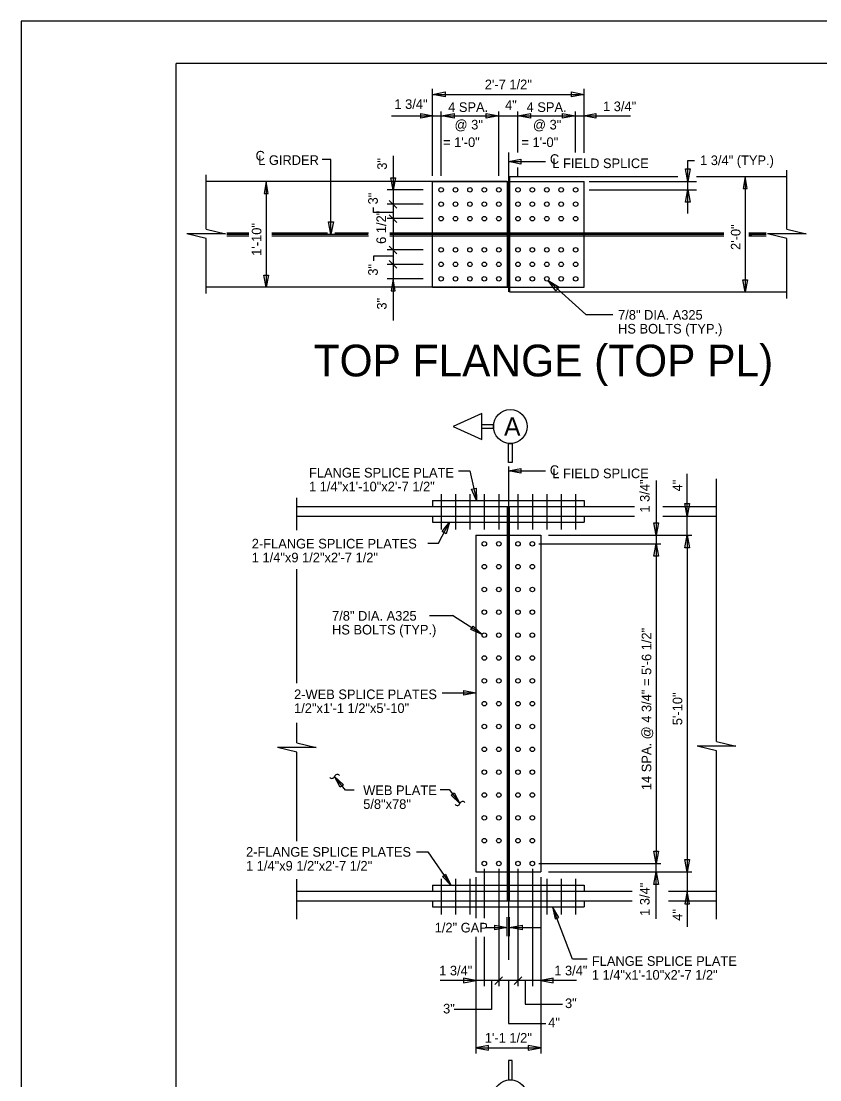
# Model space of a CAD drawing. Extents: x 1970675.2 to 1970715, y 796143 to 796167.2.
# Drawn here: x 1970675.24 to 1970685.62, y 796153.49 to 796167.25 of the extents above; entities that cross this region are included whole.
import ezdxf

# ---------------------------------------------------------------- set-up
doc = ezdxf.new("R2010")
doc.units = 0
for name, color, linetype in [('BR_AUTO DIMENSION', 7, 'Continuous'), ('BR_BORDER LINES', 7, 'Continuous'), ('BR_CENTER LINES', 7, 'Continuous'), ('BR_STRUCTURAL STEEL', 7, 'Continuous'), ('BR_TEXT', 7, 'Continuous'), ('Default', 7, 'Continuous'), ('Level 31', 7, 'Continuous')]:
    doc.layers.add(name, color=color, linetype=linetype)

msp = doc.modelspace()

# ---------------------------------------------------------------- linework, layer by layer
at = {"layer": 'BR_AUTO DIMENSION'}
for p, q in [((1970680.588, 796165.236), (1970680.588, 796166.368)), ((1970680.588, 796166.295), (1970682.557, 796166.295)), ((1970682.557, 796165.537), (1970682.557, 796166.366)), ((1970680.698, 796165.236), (1970680.698, 796166.071)), ((1970681.448, 796165.236), (1970681.448, 796166.071)), ((1970681.698, 796165.538), (1970681.698, 796166.071)), ((1970682.448, 796165.538), (1970682.448, 796166.071)), ((1970680.053, 796166.015), (1970683.16, 796166.015)), ((1970680.073, 796165.497), (1970680.073, 796163.356)), ((1970679.266, 796165.447), (1970679.15, 796165.447)), ((1970679.266, 796164.477), (1970679.266, 796165.447)), ((1970681.698, 796165.236), (1970681.698, 796165.343)), ((1970683.908, 796164.749), (1970683.908, 796165.436)), ((1970683.908, 796165.436), (1970683.995, 796165.436)), ((1970684.652, 796165.227), (1970684.652, 796163.727)), ((1970678.422, 796165.164), (1970678.422, 796163.789)), ((1970680.466, 796165.055), (1970679.998, 796165.055)), ((1970682.624, 796165.164), (1970684.018, 796165.164)), ((1970682.624, 796165.055), (1970684.018, 796165.055)), ((1970680.123, 796164.817), (1970680.024, 796164.918)), ((1970680.466, 796164.868), (1970679.998, 796164.868)), ((1970680.466, 796164.68), (1970679.998, 796164.68)), ((1970680.123, 796164.629), (1970680.024, 796164.731)), ((1970680.466, 796164.274), (1970679.998, 796164.274)), ((1970680.123, 796164.223), (1970680.024, 796164.324)), ((1970680.123, 796164.036), (1970680.024, 796164.137)), ((1970680.466, 796164.086), (1970679.998, 796164.086)), ((1970680.466, 796163.899), (1970679.998, 796163.899)), ((1970682.582, 796163.436), (1970682.091, 796163.876)), ((1970682.582, 796163.436), (1970682.93, 796163.436)), ((1970680.926, 796161.404), (1970681.072, 796161.404)), ((1970681.072, 796161.404), (1970681.159, 796161.018)), ((1970683.897, 796160.565), (1970683.897, 796161.365)), ((1970683.495, 796161.279), (1970683.495, 796160.455)), ((1970680.663, 796160.461), (1970680.809, 796160.736)), ((1970682.096, 796160.565), (1970683.96, 796160.565)), ((1970683.897, 796160.565), (1970683.897, 796156.19)), ((1970680.527, 796160.461), (1970680.663, 796160.461)), ((1970681.971, 796160.455), (1970683.557, 796160.455)), ((1970683.495, 796160.455), (1970683.495, 796156.299)), ((1970680.548, 796159.522), (1970680.845, 796159.522)), ((1970681.233, 796159.278), (1970680.845, 796159.522)), ((1970680.713, 796158.517), (1970681.151, 796158.517)), ((1970679.453, 796157.251), (1970679.312, 796157.432)), ((1970679.568, 796157.251), (1970679.453, 796157.251)), ((1970680.688, 796157.261), (1970680.802, 796157.261)), ((1970680.802, 796157.261), (1970680.943, 796157.08)), ((1970680.378, 796156.451), (1970680.524, 796156.451)), ((1970680.524, 796156.451), (1970680.825, 796156.018)), ((1970681.971, 796156.299), (1970683.557, 796156.299)), ((1970683.495, 796155.58), (1970683.495, 796156.299)), ((1970681.151, 796156.122), (1970681.151, 796155.589)), ((1970681.26, 796156.231), (1970681.26, 796155.589)), ((1970681.448, 796156.231), (1970681.448, 796154.706)), ((1970681.698, 796156.231), (1970681.698, 796154.706)), ((1970681.885, 796156.231), (1970681.885, 796154.706)), ((1970681.995, 796156.122), (1970681.995, 796153.832)), ((1970682.096, 796156.19), (1970683.96, 796156.19)), ((1970683.897, 796156.19), (1970683.897, 796155.477)), ((1970682.408, 796155.056), (1970682.149, 796155.736)), ((1970681.557, 796155.355), (1970681.557, 796155.601)), ((1970681.588, 796155.355), (1970681.588, 796155.601)), ((1970681.27, 796155.467), (1970681.557, 796155.467)), ((1970681.588, 796155.467), (1970682.004, 796155.467)), ((1970681.151, 796155.347), (1970681.151, 796153.832)), ((1970681.26, 796155.347), (1970681.26, 796154.706)), ((1970682.6, 796155.056), (1970682.408, 796155.056)), ((1970682.458, 796154.779), (1970680.687, 796154.779)), ((1970681.354, 796154.779), (1970681.354, 796154.401)), ((1970681.498, 796154.829), (1970681.397, 796154.729)), ((1970681.573, 796154.779), (1970681.573, 796154.221)), ((1970681.748, 796154.829), (1970681.647, 796154.729)), ((1970681.791, 796154.779), (1970681.791, 796154.471)), ((1970681.791, 796154.471), (1970682.278, 796154.471)), ((1970681.354, 796154.401), (1970680.868, 796154.401)), ((1970681.573, 796154.221), (1970682.059, 796154.221)), ((1970681.151, 796153.905), (1970681.995, 796153.905))]:
    msp.add_line(p, q, dxfattribs=at)
for points in [[(1970680.751, 796166.264), (1970680.588, 796166.295), (1970680.751, 796166.326)], [(1970682.395, 796166.326), (1970682.557, 796166.295), (1970682.395, 796166.264)], [(1970680.434, 796166.046), (1970680.596, 796166.015), (1970680.434, 796165.984)], [(1970680.868, 796165.984), (1970680.705, 796166.015), (1970680.868, 796166.046)], [(1970681.285, 796166.046), (1970681.448, 796166.015), (1970681.285, 796165.984)], [(1970681.86, 796165.984), (1970681.698, 796166.015), (1970681.86, 796166.046)], [(1970682.277, 796166.046), (1970682.44, 796166.015), (1970682.277, 796165.984)], [(1970682.712, 796165.984), (1970682.549, 796166.015), (1970682.712, 796166.046)], [(1970681.735, 796165.389), (1970681.573, 796165.421), (1970681.735, 796165.452)], [(1970680.103, 796165.211), (1970680.073, 796165.055), (1970680.043, 796165.211)], [(1970683.939, 796165.327), (1970683.908, 796165.164), (1970683.877, 796165.327)], [(1970684.626, 796165.071), (1970684.678, 796165.071), (1970684.652, 796165.227)], [(1970678.396, 796165.008), (1970678.448, 796165.008), (1970678.422, 796165.164)], [(1970683.877, 796164.893), (1970683.908, 796165.055), (1970683.939, 796164.893)], [(1970679.297, 796164.639), (1970679.266, 796164.477), (1970679.235, 796164.639)], [(1970678.452, 796163.945), (1970678.422, 796163.789), (1970678.392, 796163.945)], [(1970680.047, 796163.742), (1970680.099, 796163.742), (1970680.073, 796163.899)], [(1970682.191, 796163.744), (1970682.091, 796163.876), (1970682.233, 796163.791)], [(1970684.682, 796163.883), (1970684.652, 796163.727), (1970684.622, 796163.883)], [(1970681.735, 796161.371), (1970681.573, 796161.403), (1970681.735, 796161.434)], [(1970681.154, 796161.176), (1970681.159, 796161.018), (1970681.095, 796161.163)], [(1970683.929, 796160.977), (1970683.897, 796160.815), (1970683.866, 796160.977)], [(1970680.71, 796160.613), (1970680.809, 796160.736), (1970680.762, 796160.585)], [(1970683.526, 796160.727), (1970683.495, 796160.565), (1970683.463, 796160.727)], [(1970683.866, 796160.402), (1970683.897, 796160.565), (1970683.929, 796160.402)], [(1970683.463, 796160.293), (1970683.495, 796160.455), (1970683.526, 796160.293)], [(1970681.086, 796159.339), (1970681.114, 796159.383), (1970681.233, 796159.278)], [(1970680.995, 796158.547), (1970681.151, 796158.517), (1970680.995, 796158.487)], [(1970679.429, 796157.324), (1970679.387, 796157.292), (1970679.312, 796157.432)], [(1970680.827, 796157.187), (1970680.868, 796157.219), (1970680.943, 796157.08)], [(1970683.526, 796156.461), (1970683.495, 796156.299), (1970683.463, 796156.461)], [(1970683.929, 796156.352), (1970683.897, 796156.19), (1970683.866, 796156.352)], [(1970680.715, 796156.131), (1970680.757, 796156.161), (1970680.825, 796156.018)], [(1970683.463, 796156.027), (1970683.495, 796156.19), (1970683.526, 796156.027)], [(1970683.929, 796155.777), (1970683.897, 796155.94), (1970683.866, 796155.777)], [(1970682.182, 796155.581), (1970682.23, 796155.6), (1970682.149, 796155.736)], [(1970681.395, 796155.498), (1970681.557, 796155.467), (1970681.395, 796155.436)], [(1970681.751, 796155.436), (1970681.588, 796155.467), (1970681.751, 796155.498)], [(1970680.988, 796154.748), (1970681.151, 796154.779), (1970680.988, 796154.81)], [(1970682.157, 796154.81), (1970681.995, 796154.779), (1970682.157, 796154.748)], [(1970681.313, 796153.936), (1970681.151, 796153.905), (1970681.313, 796153.874)], [(1970681.832, 796153.874), (1970681.995, 796153.905), (1970681.832, 796153.936)]]:
    msp.add_lwpolyline(points, close=True, dxfattribs=at)
for points in [[(1970681.573, 796165.421), (1970682.058, 796165.421)], [(1970680.073, 796164.762), (1970679.82, 796164.762), (1970679.82, 796164.823)], [(1970680.073, 796164.192), (1970679.82, 796164.192), (1970679.82, 796164.131)], [(1970681.573, 796161.403), (1970682.058, 796161.403)]]:
    msp.add_lwpolyline(points, dxfattribs=at)
at = {"layer": 'BR_BORDER LINES'}
for p in [(1970714.286, 796166.696), (1970677.253, 796143.596)]:
    msp.add_line(p, (1970677.253, 796166.696), dxfattribs=at)
at = {"layer": 'BR_CENTER LINES'}
for p, q in [((1970681.573, 796165.541), (1970681.573, 796163.727)), ((1970677.911, 796164.477), (1970678.196, 796164.477)), ((1970678.495, 796164.477), (1970679.266, 796164.477)), ((1970679.266, 796164.477), (1970679.75, 796164.477)), ((1970680.033, 796164.477), (1970684.377, 796164.477)), ((1970684.7, 796164.477), (1970684.924, 796164.477)), ((1970684.7, 796164.477), (1970684.74, 796164.477)), ((1970681.573, 796161.459), (1970681.573, 796155.048))]:
    msp.add_line(p, q, dxfattribs=at)
at = {"layer": 'BR_STRUCTURAL STEEL'}
for p, q in [((1970681.588, 796165.227), (1970683.778, 796165.227)), ((1970681.588, 796165.227), (1970681.588, 796165.164)), ((1970684.019, 796165.227), (1970685.195, 796165.227)), ((1970681.557, 796165.164), (1970677.643, 796165.164)), ((1970680.588, 796163.789), (1970680.588, 796165.164)), ((1970680.588, 796165.164), (1970682.557, 796165.164)), ((1970681.557, 796165.164), (1970681.557, 796163.789)), ((1970681.588, 796165.164), (1970681.588, 796163.789)), ((1970682.557, 796163.789), (1970682.557, 796165.164)), ((1970677.911, 796164.496), (1970678.196, 796164.496)), ((1970677.911, 796164.457), (1970678.196, 796164.457)), ((1970678.495, 796164.496), (1970679.221, 796164.496)), ((1970678.495, 796164.457), (1970679.752, 796164.457)), ((1970679.316, 796164.496), (1970679.752, 796164.496)), ((1970680.032, 796164.496), (1970681.557, 796164.496)), ((1970680.032, 796164.457), (1970681.557, 796164.457)), ((1970681.588, 796164.496), (1970684.376, 796164.496)), ((1970681.588, 796164.457), (1970684.377, 796164.457)), ((1970684.7, 796164.496), (1970684.924, 796164.496)), ((1970684.7, 796164.457), (1970684.924, 796164.457)), ((1970684.702, 796164.461), (1970684.74, 796164.461)), ((1970681.557, 796163.789), (1970677.643, 796163.789)), ((1970680.588, 796163.789), (1970682.557, 796163.789)), ((1970681.588, 796163.789), (1970681.588, 796163.727)), ((1970681.588, 796163.727), (1970685.195, 796163.727)), ((1970680.698, 796161.099), (1970680.698, 796160.639)), ((1970680.885, 796161.099), (1970680.885, 796160.639)), ((1970681.073, 796161.099), (1970681.073, 796160.639)), ((1970681.26, 796161.099), (1970681.26, 796160.639)), ((1970681.448, 796161.099), (1970681.448, 796160.639)), ((1970681.698, 796161.099), (1970681.698, 796160.639)), ((1970681.885, 796161.099), (1970681.885, 796160.639)), ((1970682.073, 796161.099), (1970682.073, 796160.639)), ((1970682.26, 796161.099), (1970682.26, 796160.639)), ((1970682.448, 796161.099), (1970682.448, 796160.639)), ((1970678.823, 796160.94), (1970683.214, 796160.94)), ((1970680.588, 796161.018), (1970680.588, 796160.94)), ((1970680.588, 796161.018), (1970682.557, 796161.018)), ((1970680.588, 796160.94), (1970682.557, 796160.94)), ((1970681.557, 796160.94), (1970681.557, 796155.815)), ((1970681.588, 796155.815), (1970681.588, 796160.94)), ((1970682.557, 796161.018), (1970682.557, 796160.94)), ((1970683.582, 796160.94), (1970684.281, 796160.94)), ((1970678.823, 796160.815), (1970683.214, 796160.815)), ((1970680.588, 796160.815), (1970680.588, 796160.736)), ((1970680.588, 796160.815), (1970682.557, 796160.815)), ((1970682.557, 796160.815), (1970682.557, 796160.736)), ((1970683.582, 796160.815), (1970684.281, 796160.815)), ((1970680.588, 796160.736), (1970682.557, 796160.736)), ((1970681.151, 796160.565), (1970681.995, 796160.565)), ((1970681.151, 796160.565), (1970681.151, 796156.19)), ((1970681.995, 796160.565), (1970681.995, 796156.19)), ((1970681.151, 796156.19), (1970681.995, 796156.19)), ((1970680.588, 796156.018), (1970680.588, 796155.94)), ((1970680.588, 796156.018), (1970682.557, 796156.018)), ((1970680.698, 796156.099), (1970680.698, 796155.639)), ((1970680.885, 796156.099), (1970680.885, 796155.639)), ((1970681.073, 796156.099), (1970681.073, 796155.639)), ((1970681.26, 796156.099), (1970681.26, 796155.589)), ((1970681.448, 796156.099), (1970681.448, 796155.639)), ((1970681.698, 796156.099), (1970681.698, 796155.639)), ((1970681.885, 796156.099), (1970681.885, 796155.639)), ((1970682.073, 796156.099), (1970682.073, 796155.639)), ((1970682.26, 796156.099), (1970682.26, 796155.639)), ((1970682.448, 796156.099), (1970682.448, 796155.639)), ((1970682.557, 796156.018), (1970682.557, 796155.94)), ((1970678.823, 796155.94), (1970683.183, 796155.94)), ((1970680.588, 796155.94), (1970682.557, 796155.94)), ((1970683.655, 796155.94), (1970684.281, 796155.94)), ((1970678.823, 796155.815), (1970683.183, 796155.815)), ((1970680.588, 796155.815), (1970680.588, 796155.736)), ((1970680.588, 796155.815), (1970682.557, 796155.815)), ((1970680.588, 796155.736), (1970682.557, 796155.736)), ((1970682.557, 796155.815), (1970682.557, 796155.736)), ((1970683.655, 796155.815), (1970684.281, 796155.815))]:
    msp.add_line(p, q, dxfattribs=at)
for centre in [(1970680.698, 796165.055), (1970680.698, 796165.055), (1970680.885, 796165.055), (1970680.885, 796165.055), (1970681.073, 796165.055), (1970681.073, 796165.055), (1970681.26, 796165.055), (1970681.26, 796165.055), (1970681.448, 796165.055), (1970681.448, 796165.055), (1970681.698, 796165.055), (1970681.698, 796165.055), (1970681.885, 796165.055), (1970681.885, 796165.055), (1970682.073, 796165.055), (1970682.073, 796165.055), (1970682.26, 796165.055), (1970682.26, 796165.055), (1970682.448, 796165.055), (1970682.448, 796165.055), (1970680.698, 796164.868), (1970680.698, 796164.868), (1970680.885, 796164.868), (1970680.885, 796164.868), (1970681.073, 796164.868), (1970681.073, 796164.868), (1970681.26, 796164.868), (1970681.26, 796164.868), (1970681.448, 796164.868), (1970681.448, 796164.868), (1970681.698, 796164.868), (1970681.698, 796164.868), (1970681.885, 796164.868), (1970681.885, 796164.868), (1970682.073, 796164.868), (1970682.073, 796164.868), (1970682.26, 796164.868), (1970682.26, 796164.868), (1970682.448, 796164.868), (1970682.448, 796164.868), (1970680.698, 796164.68), (1970680.698, 796164.68), (1970680.885, 796164.68), (1970680.885, 796164.68), (1970681.073, 796164.68), (1970681.073, 796164.68), (1970681.26, 796164.68), (1970681.26, 796164.68), (1970681.448, 796164.68), (1970681.448, 796164.68), (1970681.698, 796164.68), (1970681.698, 796164.68), (1970681.885, 796164.68), (1970681.885, 796164.68), (1970682.073, 796164.68), (1970682.073, 796164.68), (1970682.26, 796164.68), (1970682.26, 796164.68), (1970682.448, 796164.68), (1970682.448, 796164.68), (1970680.698, 796164.274), (1970680.698, 796164.274), (1970680.885, 796164.274), (1970680.885, 796164.274), (1970681.073, 796164.274), (1970681.073, 796164.274), (1970681.26, 796164.274), (1970681.26, 796164.274), (1970681.448, 796164.274), (1970681.448, 796164.274), (1970681.698, 796164.274), (1970681.698, 796164.274), (1970681.885, 796164.274), (1970681.885, 796164.274), (1970682.073, 796164.274), (1970682.073, 796164.274), (1970682.26, 796164.274), (1970682.26, 796164.274), (1970682.448, 796164.274), (1970682.448, 796164.274), (1970680.698, 796164.086), (1970680.698, 796164.086), (1970680.885, 796164.086), (1970680.885, 796164.086), (1970681.073, 796164.086), (1970681.073, 796164.086), (1970681.26, 796164.086), (1970681.26, 796164.086), (1970681.448, 796164.086), (1970681.448, 796164.086), (1970681.698, 796164.086), (1970681.698, 796164.086), (1970681.885, 796164.086), (1970681.885, 796164.086), (1970682.073, 796164.086), (1970682.073, 796164.086), (1970682.26, 796164.086), (1970682.26, 796164.086), (1970682.448, 796164.086), (1970682.448, 796164.086), (1970680.698, 796163.899), (1970680.698, 796163.899), (1970680.885, 796163.899), (1970680.885, 796163.899), (1970681.073, 796163.899), (1970681.073, 796163.899), (1970681.26, 796163.899), (1970681.26, 796163.899), (1970681.448, 796163.899), (1970681.448, 796163.899), (1970681.698, 796163.899), (1970681.698, 796163.899), (1970681.885, 796163.899), (1970681.885, 796163.899), (1970682.073, 796163.899), (1970682.073, 796163.899), (1970682.26, 796163.899), (1970682.26, 796163.899), (1970682.448, 796163.899), (1970682.448, 796163.899), (1970681.26, 796160.455), (1970681.448, 796160.455), (1970681.698, 796160.455), (1970681.885, 796160.455), (1970681.26, 796160.158), (1970681.448, 796160.158), (1970681.698, 796160.158), (1970681.885, 796160.158), (1970681.26, 796159.861), (1970681.448, 796159.861), (1970681.698, 796159.861), (1970681.885, 796159.861), (1970681.26, 796159.565), (1970681.448, 796159.565), (1970681.698, 796159.565), (1970681.885, 796159.565), (1970681.26, 796159.268), (1970681.448, 796159.268), (1970681.698, 796159.268), (1970681.885, 796159.268), (1970681.26, 796158.971), (1970681.448, 796158.971), (1970681.698, 796158.971), (1970681.885, 796158.971), (1970681.26, 796158.674), (1970681.448, 796158.674), (1970681.698, 796158.674), (1970681.885, 796158.674), (1970681.26, 796158.377), (1970681.448, 796158.377), (1970681.698, 796158.377), (1970681.885, 796158.377), (1970681.26, 796158.08), (1970681.448, 796158.08), (1970681.698, 796158.08), (1970681.885, 796158.08), (1970681.26, 796157.783), (1970681.448, 796157.783), (1970681.698, 796157.783), (1970681.885, 796157.783), (1970681.26, 796157.486), (1970681.448, 796157.486), (1970681.698, 796157.486), (1970681.885, 796157.486), (1970681.26, 796157.19), (1970681.448, 796157.19), (1970681.698, 796157.19), (1970681.885, 796157.19), (1970681.26, 796156.893), (1970681.448, 796156.893), (1970681.698, 796156.893), (1970681.885, 796156.893), (1970681.26, 796156.596), (1970681.448, 796156.596), (1970681.698, 796156.596), (1970681.885, 796156.596), (1970681.26, 796156.299), (1970681.448, 796156.299), (1970681.698, 796156.299), (1970681.885, 796156.299)]:
    msp.add_circle(centre, 0.0293, dxfattribs=at)
at = {"layer": 'BR_TEXT'}
for points in [[(1970681.229, 796162.148), (1970680.853, 796161.979), (1970681.229, 796161.81)], [(1970681.379, 796161.954), (1970681.229, 796161.954), (1970681.229, 796162.004), (1970681.379, 796162.004)], [(1970681.623, 796161.51), (1970681.573, 796161.51), (1970681.573, 796161.76), (1970681.623, 796161.76)], [(1970681.623, 796153.739), (1970681.573, 796153.739), (1970681.573, 796153.489), (1970681.623, 796153.489)]]:
    msp.add_lwpolyline(points, close=True, dxfattribs=at)
for centre in [(1970681.598, 796161.979), (1970681.598, 796153.27)]:
    msp.add_circle(centre, 0.219, dxfattribs=at)
at = {"layer": 'Default'}
for p, q in [((1970677.643, 796164.543), (1970677.643, 796165.248)), ((1970685.195, 796164.543), (1970685.195, 796165.31)), ((1970677.643, 796164.543), (1970677.895, 796164.482)), ((1970685.195, 796164.543), (1970685.447, 796164.482)), ((1970677.895, 796164.482), (1970677.391, 796164.482)), ((1970677.643, 796164.422), (1970677.391, 796164.482)), ((1970677.643, 796163.706), (1970677.643, 796164.422)), ((1970685.447, 796164.482), (1970684.944, 796164.482)), ((1970685.195, 796164.422), (1970684.944, 796164.482)), ((1970685.195, 796163.644), (1970685.195, 796164.422)), ((1970684.281, 796157.884), (1970684.281, 796161.297)), ((1970678.823, 796160.633), (1970678.823, 796161.054)), ((1970678.823, 796158.643), (1970678.823, 796160.127)), ((1970678.823, 796157.868), (1970678.823, 796158.13)), ((1970679.074, 796157.807), (1970678.571, 796157.807)), ((1970678.823, 796157.747), (1970678.571, 796157.807)), ((1970678.823, 796157.868), (1970679.074, 796157.807)), ((1970684.532, 796157.823), (1970684.029, 796157.823)), ((1970684.281, 796157.763), (1970684.029, 796157.823)), ((1970684.281, 796157.884), (1970684.532, 796157.823)), ((1970684.281, 796155.575), (1970684.281, 796157.763)), ((1970678.823, 796156.589), (1970678.823, 796157.747)), ((1970678.823, 796155.575), (1970678.823, 796156.098))]:
    msp.add_line(p, q, dxfattribs=at)
for centre, start, end in [((1970679.277, 796157.443), 219.9477, 342.4119), ((1970679.347, 796157.421), 39.9477, 162.4119), ((1970680.908, 796157.091), 219.9477, 342.4119), ((1970680.978, 796157.069), 39.9477, 162.4119)]:
    msp.add_arc(centre, 0.0366, start, end, dxfattribs=at)
at = {"layer": 'Level 31'}
msp.add_line((1970714.836, 796167.246), (1970675.236, 796167.246), dxfattribs=at)
msp.add_lwpolyline([(1970675.236, 796167.246), (1970675.236, 796143.046), (1970714.836, 796143.046), (1970714.836, 796167.246)], dxfattribs=at)

# ---------------------------------------------------------------- texts
at = {"layer": 'BR_AUTO DIMENSION'}
for s, p in [('1 3/4"', (1970683.41, 796160.859)), ('4"', (1970683.835, 796161.135)), ('14 SPA. @ 4 3/4" = 5\'-6 1/2"', (1970683.432, 796157.253)), ('5\'-10"', (1970683.835, 796158.097)), ('1 3/4"', (1970683.41, 796155.619)), ('4"', (1970683.835, 796155.555))]:
    msp.add_text(s, height=0.125, rotation=90, dxfattribs=at).set_placement(p)
at = {"layer": 'BR_TEXT'}
for s, height, p in [('2\'-7 1/2"', 0.125, (1970681.267, 796166.362)), ('1 3/4"', 0.125, (1970680.091, 796166.106)), ('4 SPA. ', 0.125, (1970680.79, 796166.067)), ('4"', 0.125, (1970681.53, 796166.093)), ('4 SPA. ', 0.125, (1970681.81, 796166.067)), ('1 3/4"', 0.125, (1970682.804, 796166.077)), ('@ 3" ', 0.125, (1970680.873, 796165.839)), ('@ 3" ', 0.125, (1970681.893, 796165.839)), ('= 1\'-0"', 0.125, (1970680.724, 796165.611)), ('= 1\'-0"', 0.125, (1970681.744, 796165.611)), ('C', 0.125, (1970678.285, 796165.435)), ('L GIRDER', 0.125, (1970678.319, 796165.378)), ('C', 0.125, (1970682.113, 796165.392)), ('1 3/4" (TYP.)', 0.125, (1970684.066, 796165.376)), ('L FIELD SPLICE', 0.125, (1970682.144, 796165.337)), ('7/8" DIA. A325', 0.125, (1970683, 796163.367)), ('HS BOLTS (TYP.)', 0.125, (1970683, 796163.187)), ('TOP FLANGE (TOP PL)', 0.4125, (1970679.041, 796162.63)), ('A', 0.24, (1970681.517, 796161.859)), ('C', 0.125, (1970682.112, 796161.349)), ('FLANGE SPLICE PLATE', 0.125, (1970678.98, 796161.316)), ('L FIELD SPLICE', 0.125, (1970682.144, 796161.307)), ('1 1/4"x1\'-10"x2\'-7 1/2"', 0.125, (1970678.98, 796161.136)), ('2-FLANGE SPLICE PLATES', 0.125, (1970678.236, 796160.394)), ('1 1/4"x9 1/2"x2\'-7 1/2"', 0.125, (1970678.236, 796160.214)), ('7/8" DIA. A325', 0.125, (1970679.28, 796159.456)), ('HS BOLTS (TYP.)', 0.125, (1970679.28, 796159.276)), ('2-WEB SPLICE PLATES', 0.125, (1970678.786, 796158.436)), ('1/2"x1\'-1 1/2"x5\'-10"', 0.125, (1970678.786, 796158.256)), ('WEB PLATE', 0.125, (1970679.685, 796157.189)), ('5/8"x78"', 0.125, (1970679.685, 796157.009)), ('2-FLANGE SPLICE PLATES', 0.125, (1970678.161, 796156.388)), ('1 1/4"x9 1/2"x2\'-7 1/2"', 0.125, (1970678.161, 796156.208)), ('1/2" GAP', 0.125, (1970680.615, 796155.404)), ('FLANGE SPLICE PLATE', 0.125, (1970682.659, 796154.97)), ('1 3/4"', 0.125, (1970680.673, 796154.846)), ('1 3/4"', 0.125, (1970682.17, 796154.846)), ('1 1/4"x1\'-10"x2\'-7 1/2"', 0.125, (1970682.659, 796154.79)), ('3"', 0.125, (1970680.724, 796154.351)), ('3"', 0.125, (1970682.31, 796154.421)), ('4"', 0.125, (1970682.091, 796154.171)), ('1\'-1 1/2"', 0.125, (1970681.267, 796153.972))]:
    msp.add_text(s, height=height, dxfattribs=at).set_placement(p)
for s, p in [('3"', (1970679.993, 796165.316)), ('3"', (1970679.875, 796164.865)), ('6 1/2"', (1970679.982, 796164.352)), ('1\'-10"', (1970678.361, 796164.197)), ('2\'-0"', (1970684.592, 796164.273)), ('3"', (1970679.875, 796163.939)), ('3"', (1970679.989, 796163.498))]:
    msp.add_text(s, height=0.125, rotation=90, dxfattribs=at).set_placement(p)

doc.saveas('drawing.dxf')
